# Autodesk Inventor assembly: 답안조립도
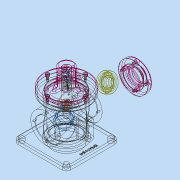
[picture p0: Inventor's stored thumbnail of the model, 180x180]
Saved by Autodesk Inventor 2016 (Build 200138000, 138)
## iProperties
Created: 2020-02
Part Number: 답안조립도
Material: 일반
Document SubType Name: Assembly
Designer: Administrator
Author: Administrator
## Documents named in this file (14)
- C:\Users\Administrator\Desktop\600206V1002\답안조립도.iam
- C:\Users\Administrator\Desktop\600206V1002\본체.ipt
- C:\Users\Administrator\Desktop\600206V1002\링크.ipt
- C:\Users\Administrator\Desktop\600206V1002\클레비스 핀 6 x 22.ipt
- 클레비스 핀 6 x 22.ipt
- C:\Users\Administrator\Desktop\600206V1002\E-링.ipt
- C:\Users\Administrator\Desktop\600206V1002\슬라이더.ipt
- C:\Users\Administrator\Desktop\600206V1002\가변스프링.ipt
- C:\Users\Administrator\Desktop\600206V1002\덮개.ipt
- C:\Users\Administrator\Desktop\600206V1002\개스킷 B.ipt
- C:\Users\Administrator\Desktop\600206V1002\육각 소켓 머리 볼트 M4 x 10.ipt
- C:\Users\Administrator\Desktop\600206V1002\베어링 17 x 40 x 12.ipt
- C:\Users\Administrator\Desktop\600206V1002\뒤커버.ipt
- C:\Users\Administrator\Desktop\600206V1002\개스킷 A.ipt
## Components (4 placed, 4 different names)
1. E-링:1
2. 가변스프링:1
3. 개스킷 B:1
4. 개스킷 A:1
